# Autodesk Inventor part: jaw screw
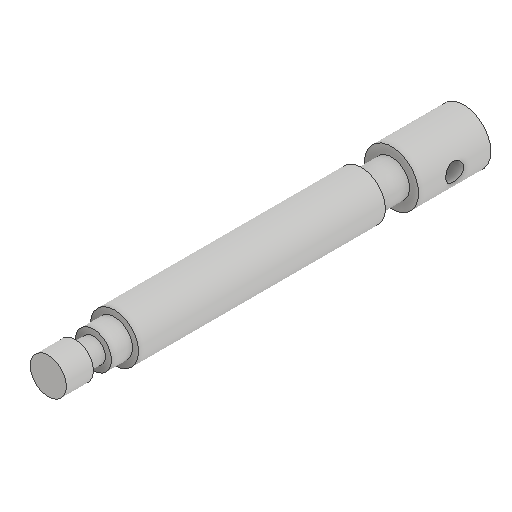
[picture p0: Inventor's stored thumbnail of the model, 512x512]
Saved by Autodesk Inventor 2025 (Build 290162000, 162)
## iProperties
Created: 2016-03
Part Number: jaw screw
Material: Generic
Document SubType Name: Modeling
Designer: Sandeep
Density: 1 g/cm^3
Appearance: Default
Mass: 25.5852 g
Surface Area: 75.8462 cm^2
Volume: 25.5852 cm^3
Author: Sandeep
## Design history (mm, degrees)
sketch "Sketch1"
  geometry: L1 (0, -138)-(-6, -138); L2 (-6, -116)-(-6, -116); L3 (-6, -116)-(-8, -116); L4 (-8, -116)-(-8, -34); L5 (-8, -34)-(-6, -34); L6 (-6, -34)-(-6, -24); L7 (-6, -24)-(-9, -24); L8 (-9, -24)-(-9, 0); L9 (-9, 0)-(0, 0); L10 (0, 0)-(0, -138); L11 (0, 0)-(0, 14.581); L12 (-6, -116)-(-6, -123); L13 (-6, -123)-(-4, -123); L14 (-4, -123)-(-4, -129); L15 (-4, -129)-(-6, -129); L16 (-6, -129)-(-6, -138); 1 other entity
  constraints: 32 end point, 10 perpendicular, 3 point on line, 3 vertical, 1 coincident, 1 horizontal, 2 other
  dimensions: "d0" = 18 diameter of L8 L11; "d1" = 12 diameter of L6 L11; "d3" = 24 distance of L7.end L8.end; "d4" = 10 distance of L5.end L6.end; "d5" = 82 distance of L3.end L4.end; "d6" = 138 distance between parallel lines of L1 L9; "d8" = 16 diameter of L4 L11; "d10" = 6 distance of L13.end L14.end; "d11" = 9 distance of L15.end L1.end; "d12" = 8 diameter of L14 L11
revolve "Revolution1" sketch "Sketch1" stored, may be unused: angle "d9" = 90 deg
sketch "Sketch2"
  geometry: L1 (0, -9)-(0, 9) reference; L2 (0, 0)-(-20.975, 0); C1 r 3 at (-12, 0)
  constraints: 2 end point, 1 centre point, 1 horizontal, 1 point on line
  dimensions: "d13" = 6 diameter of C1; "d14" = 12 distance from line of L1 C1.centre
extrude "Extrusion1" cut sketch "Sketch2" distance "d15" = 25; taper "d16" = 0 deg
body "Solid1"
